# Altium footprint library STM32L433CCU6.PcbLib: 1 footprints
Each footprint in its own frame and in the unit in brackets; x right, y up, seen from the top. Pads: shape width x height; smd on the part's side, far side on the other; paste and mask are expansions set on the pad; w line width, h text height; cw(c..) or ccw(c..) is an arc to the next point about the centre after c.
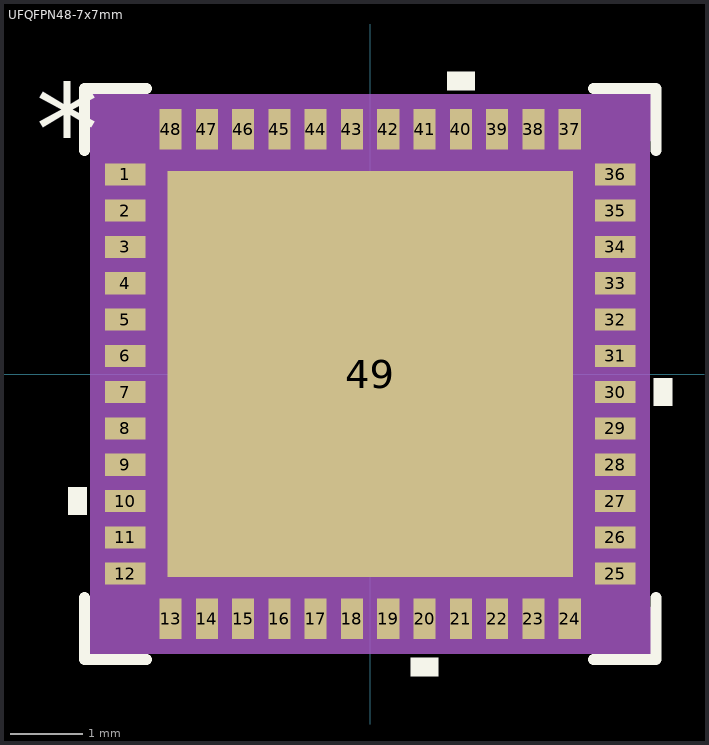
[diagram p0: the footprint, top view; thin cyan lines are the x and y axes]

## UFQFPN48-7x7mm [mil]
pads (49):
  rect 22x12 smd paste-11 mask-11: 1(-132.87,108.3) 2(-132.87,88.61) 3(-132.87,68.92) 4(-132.87,49.23) 5(-132.87,29.54) 6(-132.87,9.85) 7(-132.87,-9.85) 8(-132.87,-29.54) 9(-132.87,-49.23) 10(-132.87,-68.92) 11(-132.87,-88.61) 12(-132.87,-108.3) 25(132.87,-108.3) 26(132.87,-88.61) 27(132.87,-68.92) 28(132.87,-49.23) 29(132.87,-29.54) 30(132.87,-9.85) 31(132.87,9.85) 32(132.87,29.54) 33(132.87,49.23) 34(132.87,68.92) 35(132.87,88.61) 36(132.87,108.3)
  rect 12x22 smd paste-11 mask-11: 13(-108.3,-132.87) 14(-88.61,-132.87) 15(-68.92,-132.87) 16(-49.23,-132.87) 17(-29.54,-132.87) 18(-9.85,-132.87) 19(9.85,-132.87) 20(29.54,-132.87) 21(49.23,-132.87) 22(68.92,-132.87) 23(88.61,-132.87) 24(108.3,-132.87) 37(108.3,132.87) 38(88.61,132.87) 39(68.92,132.87) 40(49.23,132.87) 41(29.54,132.87) 42(9.85,132.87) 43(-9.85,132.87) 44(-29.54,132.87) 45(-49.23,132.87) 46(-68.92,132.87) 47(-88.61,132.87) 48(-108.3,132.87)
  rect 220x220 smd paste-110 mask-110: 49(0,0)
Top Overlay:
  region: -153.87,-61.41 -163.87,-61.41 -163.87,-76.42 -153.87,-76.42
  region: 37.03,-153.87 22.04,-153.87 22.04,-163.87 37.03,-163.87
  region: 153.87,-2.35 163.87,-2.35 163.87,-17.34 153.87,-17.34
  region: 56.73,153.87 41.73,153.87 41.73,163.87 56.73,163.87
  lines w6: -155,-121.21 -155,-155 -121.21,-155 ; -155,121.21 -155,155 -121.21,155 ; 121.21,-155 155,-155 155,-121.21 ; 121.21,155 155,155 155,121.21
  text "*" at -181.37,108.14 h50
Top Paste:
  drawing of 64 lines, arcs and shapes, not listed
Top Solder:
  drawing of 48 lines, arcs and shapes, not listed
Mechanical 13:
  drawing of 197 lines, arcs and shapes, not listed
  text "*" at -124.37,93.14 h50
Mechanical 15:
  region: -128.29,-150 -150,-150 -150,-128.29 -148.87,-128.29 -148.87,128.29 -150,128.29 -150,150 -128.29,150 -128.29,148.87 128.29,148.87 128.29,150 150,150 150,128.29 148.87,128.29 148.87,-128.29 150,-128.29 150,-150 128.29,-150 128.29,-148.87 -128.29,-148.87
  lines w6: -150,-150 -150,-128.29 -148.87,-128.29 -148.87,128.29 -150,128.29 -150,150 -128.29,150 -128.29,148.87 128.29,148.87 128.29,150 150,150 150,128.29 148.87,128.29 148.87,-128.29 150,-128.29 150,-150 128.29,-150 128.29,-148.87 -128.29,-148.87 -128.29,-150 -150,-150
